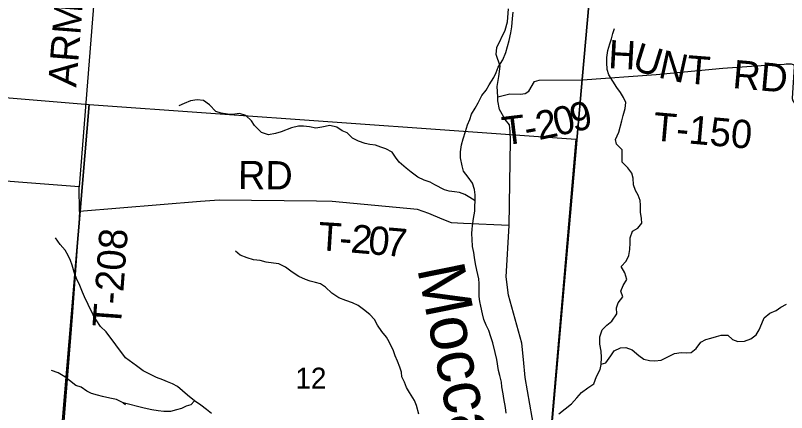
# Model space of a CAD drawing. Extents: x 0 to 42.5, y 0 to 22.
# Drawn here: x 7.815 to 8.588, y 17.814 to 18.213 of the extents above; entities that cross this region are included whole.
import ezdxf

# ---------------------------------------------------------------- set-up
doc = ezdxf.new("R2010")
doc.units = 0
for name, color, linetype in [('GM_X_Interchange_Ramps', 7, 'Continuous'), ('GM_X_Minor_River', 7, 'Continuous'), ('GM_X_Minor_River_Text', 7, 'Continuous'), ('GM_X_Section', 7, 'Continuous'), ('GM_X_Section_Text', 7, 'Continuous'), ('GM_X_Township', 7, 'Continuous'), ('GM_X_Township_Road', 7, 'Continuous'), ('GM_X_Township_Road_Text', 7, 'Continuous'), ('SH_Cut_Line', 7, 'Continuous')]:
    doc.layers.add(name, color=color, linetype=linetype)

msp = doc.modelspace()

# ---------------------------------------------------------------- linework, layer by layer
at = {"layer": 'GM_X_Interchange_Ramps'}
msp.add_lwpolyline([(8.9, 15.53758), (8.9, 19.05381), (8.80207, 19.06082), (8.79715, 19.06117), (8.45529, 19.08562), (8.42249, 18.59682), (8.4216, 18.58362), (8.41233, 18.47844), (8.38323, 18.14846), (8.33786, 17.63394), (8.30797, 17.29222), (8.30866, 17.28459), (8.30841, 17.27648), (8.30737, 17.26941), (8.29023, 17.08765), (8.28773, 17.0646), (8.28228, 16.99116), (8.27401, 16.89234), (8.25723, 16.70556), (8.24802, 16.59431), (8.24781, 16.59008), (8.17933, 15.79111)], dxfattribs=at)
at = {"layer": 'GM_X_Minor_River'}
for p, q in [((8.41392, 18.19482), (8.41564, 18.19975)), ((8.41257, 18.18933), (8.41392, 18.19482)), ((8.40892, 18.17759), (8.41084, 18.18422)), ((8.41084, 18.18422), (8.41257, 18.18933)), ((8.40794, 18.17076), (8.40892, 18.17759)), ((8.40773, 18.16564), (8.40794, 18.17076)), ((8.40827, 18.15862), (8.40773, 18.16564)), ((8.40977, 18.15312), (8.40827, 18.15862)), ((8.41372, 18.14685), (8.40977, 18.15312)), ((8.41787, 18.14038), (8.41372, 18.14685)), ((8.42145, 18.13544), (8.41787, 18.14038)), ((8.42466, 18.13049), (8.42145, 18.13544)), ((8.42672, 18.12555), (8.42466, 18.13049)), ((8.42632, 18.11949), (8.42672, 18.12555)), ((8.42286, 18.10717), (8.42402, 18.11248)), ((8.42402, 18.11248), (8.42632, 18.11949)), ((8.41997, 18.09581), (8.42286, 18.10717)), ((8.41633, 18.08842), (8.41997, 18.09581)), ((8.41745, 18.08368), (8.41633, 18.08842)), ((8.42312, 18.07797), (8.41745, 18.08368)), ((8.42328, 18.0719), (8.42312, 18.07797)), ((8.42326, 18.06564), (8.42328, 18.0719)), ((8.42873, 18.05993), (8.42326, 18.06564)), ((8.43269, 18.05441), (8.42873, 18.05993)), ((8.43419, 18.04948), (8.43269, 18.05441)), ((8.43454, 18.04284), (8.43419, 18.04948)), ((8.43642, 18.03714), (8.43454, 18.04284)), ((8.43924, 18.03239), (8.43642, 18.03714)), ((8.44112, 18.02707), (8.43924, 18.03239)), ((8.44167, 18.02233), (8.44112, 18.02707)), ((8.44145, 18.01531), (8.44167, 18.02233)), ((8.44256, 18.00905), (8.44145, 18.01531)), ((8.43892, 17.9992), (8.44292, 18.00431)), ((8.44292, 18.00431), (8.44256, 18.00905)), ((8.4336, 17.99619), (8.43892, 17.9992)), ((8.43109, 17.98444), (8.43111, 17.98956)), ((8.43111, 17.98956), (8.4336, 17.99619)), ((8.43068, 17.978), (8.43109, 17.98444)), ((8.42971, 17.97193), (8.43068, 17.978)), ((8.42208, 17.96096), (8.42722, 17.96625)), ((8.42722, 17.96625), (8.42971, 17.97193)), ((8.42585, 17.9545), (8.42208, 17.96096)), ((8.42772, 17.94785), (8.42585, 17.9545)), ((8.42409, 17.9418), (8.42772, 17.94785)), ((8.42179, 17.93593), (8.42409, 17.9418)), ((8.42386, 17.93042), (8.42179, 17.93593)), ((8.41909, 17.92437), (8.42386, 17.93042)), ((8.41737, 17.91945), (8.41909, 17.92437)), ((8.41772, 17.91319), (8.41737, 17.91945)), ((8.57757, 17.91655), (8.58232, 17.91995)), ((8.58232, 17.91995), (8.58803, 17.92315)), ((8.41276, 17.90581), (8.41772, 17.91319)), ((8.5656, 17.9092), (8.5713, 17.91411)), ((8.5713, 17.91411), (8.57757, 17.91655)), ((8.40782, 17.90204), (8.41276, 17.90581)), ((8.56311, 17.90352), (8.5656, 17.9092)), ((8.40094, 17.8903), (8.40325, 17.89712)), ((8.40325, 17.89712), (8.40782, 17.90204)), ((8.55738, 17.89236), (8.56062, 17.89728)), ((8.56062, 17.89728), (8.56311, 17.90352)), ((8.40072, 17.88272), (8.40094, 17.8903)), ((8.50692, 17.88762), (8.51205, 17.88874)), ((8.51205, 17.88874), (8.51774, 17.89042)), ((8.51774, 17.89042), (8.52249, 17.89192)), ((8.52249, 17.89192), (8.52893, 17.8919)), ((8.52893, 17.8919), (8.53385, 17.88771)), ((8.55205, 17.88821), (8.55738, 17.89236)), ((8.40221, 17.8757), (8.40072, 17.88272)), ((8.49721, 17.87837), (8.50198, 17.88479)), ((8.50198, 17.88479), (8.50692, 17.88762)), ((8.53385, 17.88771), (8.53896, 17.8856)), ((8.53896, 17.8856), (8.54578, 17.88576)), ((8.54578, 17.88576), (8.55205, 17.88821)), ((8.40238, 17.86944), (8.40221, 17.8757)), ((8.41167, 17.87111), (8.41511, 17.87621)), ((8.41511, 17.87621), (8.42157, 17.87903)), ((8.42157, 17.87903), (8.42688, 17.87939)), ((8.42688, 17.87939), (8.43331, 17.87709)), ((8.43331, 17.87709), (8.43974, 17.87157)), ((8.46817, 17.86975), (8.47558, 17.87352)), ((8.47558, 17.87352), (8.48241, 17.87444)), ((8.48241, 17.87444), (8.48734, 17.87404)), ((8.48734, 17.87404), (8.49227, 17.87459)), ((8.49227, 17.87459), (8.49721, 17.87837)), ((8.40197, 17.86261), (8.40238, 17.86944)), ((8.40672, 17.86411), (8.41167, 17.87111)), ((8.43974, 17.87157), (8.44484, 17.86776)), ((8.44484, 17.86776), (8.45052, 17.86641)), ((8.45052, 17.86641), (8.45602, 17.8662)), ((8.45602, 17.8662), (8.46228, 17.86693)), ((8.46228, 17.86693), (8.46817, 17.86975)), ((8.40119, 17.8573), (8.40197, 17.86261)), ((8.40199, 17.86295), (8.40672, 17.86411)), ((8.39469, 17.8431), (8.39737, 17.85049)), ((8.39737, 17.85049), (8.40119, 17.8573)), ((8.38879, 17.83896), (8.39469, 17.8431)), ((8.37757, 17.82895), (8.38233, 17.83424)), ((8.38233, 17.83424), (8.38879, 17.83896)), ((8.37223, 17.8229), (8.37757, 17.82895)), ((8.36615, 17.81799), (8.37223, 17.8229)), ((8.35968, 17.81309), (8.36615, 17.81799))]:
    msp.add_line(p, q, dxfattribs=at)
for points in [[(8.26619, 18.09631), (8.26828, 18.10314), (8.27057, 18.10844), (8.27229, 18.11375), (8.27571, 18.11963), (8.27876, 18.12513), (8.28257, 18.13252), (8.28694, 18.13783), (8.28979, 18.14332), (8.29436, 18.15052), (8.29684, 18.15545), (8.29874, 18.16095), (8.3035, 18.16834), (8.30655, 18.17555), (8.30827, 18.18162), (8.30998, 18.1875), (8.3117, 18.19527), (8.31247, 18.20134), (8.31325, 18.20969), (8.31383, 18.21614)], [(8.27574, 18.02665), (8.27043, 18.03008), (8.2655, 18.03312), (8.26, 18.03503), (8.25507, 18.03561), (8.24976, 18.03638), (8.24502, 18.03772), (8.23536, 18.04286), (8.23062, 18.04553), (8.22455, 18.04762), (8.21848, 18.05048), (8.21166, 18.05562), (8.20655, 18.05961), (8.19973, 18.0657), (8.19595, 18.07045), (8.19273, 18.07558), (8.1861, 18.07901), (8.18136, 18.08073), (8.17586, 18.08244), (8.17036, 18.08341), (8.16562, 18.08417), (8.15898, 18.08646), (8.15273, 18.0897), (8.14742, 18.09503), (8.14249, 18.09712), (8.137, 18.10074), (8.13017, 18.10227), (8.12201, 18.10058), (8.11594, 18.09964), (8.10968, 18.10117), (8.1038, 18.10175), (8.09868, 18.10157), (8.09166, 18.09988), (8.08122, 18.0961), (8.07552, 18.09422), (8.06869, 18.0929), (8.06148, 18.09538), (8.05448, 18.10242), (8.05145, 18.10717), (8.04596, 18.1123), (8.0397, 18.1144), (8.03477, 18.11365), (8.03002, 18.11347), (8.02111, 18.11482), (8.0158, 18.11654), (8.00936, 18.12319), (8.00349, 18.12738), (7.99723, 18.12815), (7.9904, 18.12721), (7.98413, 18.12438), (7.97882, 18.12211)], [(8.30685, 17.8135), (8.3061, 17.81938), (8.30459, 17.8283), (8.30403, 17.83305), (8.30253, 17.84007), (8.30216, 17.84482), (8.30065, 17.85127), (8.29933, 17.8564), (8.29765, 17.86741), (8.29595, 17.87462), (8.2935, 17.88411), (8.29162, 17.89038), (8.28954, 17.89664), (8.28689, 17.90196), (8.28463, 17.90766), (8.28331, 17.91335), (8.28143, 17.92095), (8.28049, 17.92569), (8.27974, 17.93082), (8.27976, 17.94372), (8.27939, 17.94847), (8.27751, 17.9572), (8.27619, 17.96365), (8.27506, 17.96992), (8.27431, 17.97504), (8.27319, 17.98093), (8.27263, 17.98814), (8.27245, 17.99345), (8.27284, 17.99857), (8.27361, 18.00389), (8.27419, 18.00901), (8.27534, 18.01641), (8.27554, 18.02115), (8.27574, 18.02665), (8.27575, 18.03272), (8.275, 18.03823), (8.27311, 18.04449), (8.26895, 18.05038), (8.26403, 18.05647), (8.26271, 18.06197), (8.26121, 18.06994), (8.26103, 18.07602), (8.26199, 18.08285), (8.26371, 18.08891), (8.26619, 18.09631)], [(7.92528, 17.86902), (7.90602, 17.8951), (7.90011, 17.90046), (7.89572, 17.90714), (7.89248, 17.91286), (7.88791, 17.92277), (7.8841, 17.9304), (7.88201, 17.93516), (7.87954, 17.94164), (7.8763, 17.94888), (7.87383, 17.95517), (7.87193, 17.96202), (7.87003, 17.96697), (7.86794, 17.97193), (7.86489, 17.97727), (7.85993, 17.983), (7.85516, 17.98949)], [(8.2192, 17.81272), (8.21712, 17.82126), (8.21505, 17.8262), (8.21013, 17.83437), (8.2071, 17.8395), (8.20502, 17.84463), (8.20238, 17.85014), (8.20182, 17.85488), (8.20031, 17.85963), (8.19804, 17.86589), (8.19559, 17.87102), (8.19389, 17.87634), (8.18973, 17.88526), (8.18708, 17.89001), (8.18235, 17.89572), (8.178, 17.90199), (8.17478, 17.9075), (8.17024, 17.91263), (8.16399, 17.91776), (8.15868, 17.92157), (8.153, 17.92443), (8.14617, 17.92672), (8.13897, 17.92939), (8.13215, 17.93415), (8.1259, 17.94023), (8.12078, 17.94328), (8.11566, 17.9448), (8.11054, 17.94595), (8.10561, 17.94767), (8.09898, 17.95091), (8.09234, 17.9551), (8.08552, 17.96023), (8.07889, 17.96347), (8.07358, 17.96405), (8.06637, 17.96501), (8.06011, 17.96673), (8.05367, 17.96751), (8.04722, 17.96961), (8.04021, 17.97228), (8.03547, 17.97608)], [(8.01146, 17.81313), (8.00635, 17.81732), (8.00085, 17.82169), (7.99441, 17.82607), (7.98759, 17.83177), (7.98248, 17.83596), (7.97755, 17.84052), (7.97244, 17.84319), (7.96751, 17.8451), (7.96277, 17.847), (7.95651, 17.84948), (7.94817, 17.85348), (7.94305, 17.85615), (7.93642, 17.8611), (7.92528, 17.86902)], [(7.92528, 17.82225), (7.92308, 17.82393), (7.91625, 17.82717), (7.90943, 17.82851), (7.90222, 17.83023), (7.89729, 17.83176), (7.89122, 17.83329), (7.88648, 17.83577), (7.8808, 17.83957), (7.87549, 17.84129), (7.86924, 17.84624), (7.86431, 17.85023), (7.85768, 17.85404), (7.85104, 17.85633)], [(7.99441, 17.82607), (7.9908, 17.82209), (7.98605, 17.82058), (7.98131, 17.81831), (7.97637, 17.81681), (7.9703, 17.8153), (7.96385, 17.81531), (7.95816, 17.81589), (7.95152, 17.81685), (7.94393, 17.81858), (7.92308, 17.82393), (7.92528, 17.82225)]]:
    msp.add_lwpolyline(points, dxfattribs=at)
at = {"layer": 'GM_X_Section'}
for points in [[(7.88871, 18.12341), (7.84665, 17.62408), (7.35243, 17.66688), (7.39563, 18.16469)], [(7.88871, 18.12341), (8.37679, 18.08863), (8.33774, 17.63462), (8.33335, 17.58203), (7.84665, 17.62408)]]:
    msp.add_lwpolyline(points, close=True, dxfattribs=at)
at = {"layer": 'GM_X_Township'}
msp.add_lwpolyline([(7.68737, 18.6472), (7.92905, 18.62689), (8.11105, 18.61092), (8.2565, 18.59969), (8.27414, 18.60201), (8.28296, 18.60185), (8.29503, 18.59876), (8.30146, 18.59566), (8.4216, 18.58362), (8.41233, 18.47844), (8.38323, 18.14846), (8.33786, 17.63394), (8.30797, 17.29222)], dxfattribs=at)
at = {"layer": 'GM_X_Township_Road'}
msp.add_line((7.87917, 18.01606), (7.8789, 18.04068), dxfattribs=at)
for points in [[(7.92916, 18.62662), (7.91941, 18.54666), (7.91012, 18.42624), (7.89878, 18.29405), (7.8789, 18.04068)], [(8.33521, 17.79585), (8.32605, 17.84957), (8.32419, 17.86765), (8.32269, 17.88383), (8.30909, 17.93209), (8.30686, 17.95056), (8.30998, 18.00204), (8.31106, 18.08739), (8.31079, 18.09633), (8.31012, 18.10299), (8.30602, 18.10836), (8.30027, 18.11832), (8.29868, 18.12708), (8.29846, 18.13119), (8.29792, 18.14154), (8.29956, 18.1514), (8.30083, 18.16204), (8.297, 18.17368), (8.29746, 18.18052), (8.30583, 18.19791), (8.30821, 18.20624), (8.30932, 18.21954)], [(8.38334, 18.1482), (8.45732, 18.15357), (8.52395, 18.15986), (8.57212, 18.16315)], [(8.57212, 18.16315), (8.58547, 18.16406), (8.58745, 18.16416), (8.59043, 18.16424), (8.59268, 18.16428), (8.59447, 18.16353), (8.59551, 18.16264), (8.59573, 18.16131), (8.59388, 18.13499), (8.59373, 18.12936), (8.59418, 18.12706), (8.59544, 18.12557), (8.59707, 18.12454), (8.59952, 18.12424), (8.61754, 18.1222)], [(8.29846, 18.13119), (8.31048, 18.13409), (8.3211, 18.13381), (8.32604, 18.13452), (8.32948, 18.13677), (8.33544, 18.1464), (8.33982, 18.14769), (8.38334, 18.1482)], [(7.8789, 18.04068), (7.75285, 18.05037), (7.71084, 18.05411), (7.67678, 18.05737), (7.66825, 18.05728), (7.65883, 18.06139), (7.63871, 18.07323), (7.63101, 18.07807)], [(8.30998, 18.00204), (8.26416, 18.00392), (8.25204, 18.00464), (8.24261, 18.00836), (8.22943, 18.01403), (8.21792, 18.01817), (8.13258, 18.02623), (8.11686, 18.02642), (8.01912, 18.0274), (8.00053, 18.02591), (7.87917, 18.01606)], [(7.87917, 18.01606), (7.87848, 18.00405), (7.87171, 17.91073), (7.86324, 17.80122), (7.86364, 17.79557)]]:
    msp.add_lwpolyline(points, dxfattribs=at)
at = {"layer": 'SH_Cut_Line'}
for points in [[(8.9, 14.1), (8.9, 19.05381), (8.80207, 19.06082), (8.79715, 19.06117), (8.45529, 19.08562), (8.42249, 18.59682), (8.4216, 18.58362), (8.41233, 18.47844), (8.38323, 18.14846), (8.33786, 17.63394), (8.30797, 17.29222), (8.30866, 17.28459), (8.30841, 17.27648), (8.30737, 17.26941), (8.29023, 17.08765), (8.28773, 17.0646), (8.28228, 16.99116), (8.27401, 16.89234), (8.25723, 16.70556), (8.24802, 16.59431), (8.24781, 16.59008), (8.17933, 15.79111)], [(8.30797, 17.29222), (8.33786, 17.63394), (8.38323, 18.14846), (8.41233, 18.47844), (8.4216, 18.58362), (8.30146, 18.59566), (8.29503, 18.59876), (8.28296, 18.60185), (8.27414, 18.60201), (8.2565, 18.59969), (8.11105, 18.61092), (7.92905, 18.62689), (7.68737, 18.6472)]]:
    msp.add_lwpolyline(points, dxfattribs=at)

# ---------------------------------------------------------------- texts
at = {"layer": 'GM_X_Minor_River_Text'}
msp.add_text('Moccasin', height=0.047349, rotation=281.44705, dxfattribs=at).set_placement((8.21753, 17.95899))
at = {"layer": 'GM_X_Section_Text'}
msp.add_text('12', height=0.020928, rotation=0.00001, dxfattribs=at).set_placement((8.09557, 17.83835))
at = {"layer": 'GM_X_Township_Road_Text'}
for s, height, rotation, p in [('ARMSTRONG', 0.028409, 85.50883, (7.87588, 18.14023)), ('H', 0.02841, 356.85475, (8.40871, 18.1599)), ('U', 0.02841, 342.64808, (8.43192, 18.15885)), ('N', 0.02841, 347.55706, (8.45838, 18.1507)), ('T', 0.02841, 355.44329, (8.48702, 18.14468)), ('RD', 0.028409, 354.96682, (8.53322, 18.14002)), ('0', 0.02841, 13.26112, (8.35752, 18.09141)), ('9', 0.02841, 13.61684, (8.37475, 18.09546)), ('T', 0.02841, 6.97724, (8.3045, 18.08249)), ('2', 0.02841, 11.91973, (8.33969, 18.08763)), ('T-150', 0.028409, 354.96682, (8.45331, 18.08752)), ('-', 0.02841, 10.50716, (8.32747, 18.08536)), ('RD', 0.028409, 359.50542, (8.03795, 18.0385)), ('T', 0.02841, 356.40415, (8.11771, 17.97723)), ('T-208', 0.028409, 85.78371, (7.92044, 17.89904)), ('2', 0.02841, 355.06306, (8.15037, 17.97495)), ('0', 0.02841, 354.96929, (8.16779, 17.97345)), ('7', 0.02841, 354.95069, (8.18522, 17.97191)), ('-', 0.02841, 355.31544, (8.13877, 17.9759))]:
    msp.add_text(s, height=height, rotation=rotation, dxfattribs=at).set_placement(p)

doc.saveas('drawing.dxf')
